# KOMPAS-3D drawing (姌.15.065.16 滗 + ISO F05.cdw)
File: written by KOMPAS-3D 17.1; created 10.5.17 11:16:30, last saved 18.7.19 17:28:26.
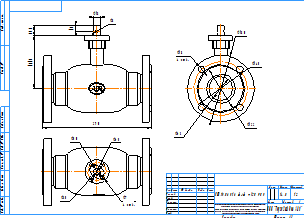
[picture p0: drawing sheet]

Sheet 1: A3, landscape

Title block, sheet 1: name: КШ.15.065.16 ф/ф + ISO F05; mass: 14,8; sheets: 1; organisation: ООО "Торговый дом АДЛ"; sheet format: A3; stored path: C:\Users\kka\KOMPAS_Work\Модели кранов для исследований\DN80\КШГ.15.065.16 ФФ ГЧ _ Шаровой кран БИВАЛ Ду50 Ру1,6 МПа полнопроходной фланцевый Габаритный чертеж.cdw

Views: Вид 1, Проекционный вид 2, Проекционный вид 4
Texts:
  Klimkovich
  ADL
  Рама для чертежей
  Лит-Масса-Масштаб
  Материал-Предприятие
  Масштаб
  Изм.
  Лист
  № докум.
  Подп.
  Дата
  Лит.
  Разраб.
  Пров.
  Т.контр.
  Листов
  Внимание! Данный продукт является объектом авторского права ООО «Торговый Дом АДЛ».
  Запрещается изменение, копирование, распространение
  (в том числе путем копирования на другие сайты и ресурсы в Интернете)
  или любое иное использование информации и объектов без предварительного
  согласия правообладателя (ООО «Торговый Дом АДЛ»).
  Н.контр.
  Утв.
  Изменение
  Номер документа
  Подпись
  Обозначение документа
  Наименование изделия
  Масса изделия по ГОСТ 2.109-73
  Порядковый номер листа
  Общее количество листов в документе
  Характер работы, выполненной лицом, подписавшим документ
  Наименование или индекс предприятия, выпускающего документ
  Инв. № подл.
  Подп. и дата
  Взам. инв. №
  Инв. № дубл.
  Инвентарный номер подлинника по ГОСТ 2.501-68
  Подпись принявшего подлинник в отдел технической документации
  Инвентарный номер подлинника, взамен которого выпущен данный подлинник
  Инвентарный номер дубликата по ГОСТ 2.502-68
  Подпись принявшего дубликат в отдел технической документации
  Справ. №
  Перв. примен.
  Обозначение документа, взамен или на основании которого выпущен данный документ
  Обозначение документа, в котором впервые записан данный документ
  Подпись лица, копировавшего чертеж
  Обозначение формата листа
  !Рама для чертежа
Dimensions and other numbers on the sheet: 290; 141,3; 27,5; 15; 8; 18; 180; 145; 122; 63; 4 отв.; 65; 50; 7; 35; 1:2; 1; 14,8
